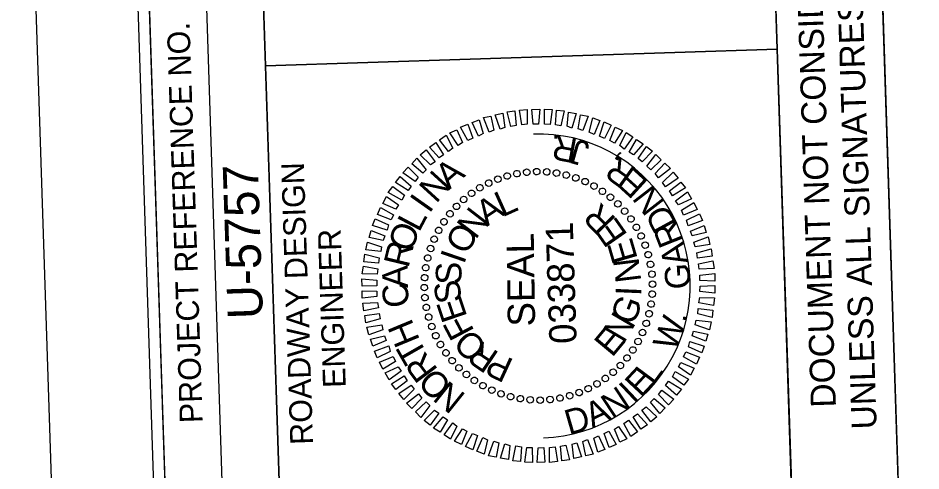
# Model space of a CAD drawing. Extents: x 1627314 to 1628469, y 762309 to 764245.
# Drawn here: x 1627314.2 to 1627512.6, y 763788.2 to 763887.6 of the extents above; entities that cross this region are included whole.
import ezdxf

# ---------------------------------------------------------------- set-up
doc = ezdxf.new("R2010")
doc.units = 0
for name, color, linetype in [('Old_Level_2', 7, 'Continuous'), ('Scratch_Level_0', 7, 'Continuous'), ('Sheet Data Field CELL', 7, 'Continuous'), ('Sheet Plot Border Inside CELL', 7, 'Continuous'), ('Sheet Plot Border Outside CELL', 7, 'Continuous'), ('Sheet Professional Seal CELL', 7, 'Continuous'), ('Sheet Profile CELL', 7, 'Continuous'), ('Sheet Profile Grid Major CELL', 7, 'Continuous'), ('Sheet Profile Grid Minor CELL', 7, 'Continuous'), ('Sheet Sticker Exception Certification CELL', 7, 'Continuous')]:
    doc.layers.add(name, color=color, linetype=linetype)

msp = doc.modelspace()

# ---------------------------------------------------------------- linework, layer by layer
at = {"layer": 'Old_Level_2'}
msp.add_lwpolyline([(1627507.79, 763781.61), (1627501.25, 763981.49), (1627565.16, 763983.58), (1627571.7, 763783.7)], close=True, dxfattribs=at)
at = {"layer": 'Scratch_Level_0'}
msp.add_arc((1627428.56, 763828.82), 33.36, 271.8735, 91.8735, dxfattribs=at)
at = {"layer": 'Sheet Plot Border Inside CELL'}
msp.add_lwpolyline([(1628446.34, 762357.53), (1628391.86, 764023.14), (1627337.33, 763988.65), (1627391.81, 762323.04)], close=True, dxfattribs=at)
at = {"layer": 'Sheet Plot Border Outside CELL'}
msp.add_lwpolyline([(1628469.21, 762345.27), (1628413.63, 764044.37), (1627314.22, 764008.4), (1627369.79, 762309.31)], close=True, dxfattribs=at)
at = {"layer": 'Sheet Professional Seal CELL'}
for p, q in [((1627419.59, 763852.29), (1627419.59, 763852.29)), ((1627421.67, 763852.96), (1627421.67, 763852.96)), ((1627423.86, 763853.43), (1627423.86, 763853.43)), ((1627426, 763853.8), (1627426, 763853.8)), ((1627428.19, 763853.92), (1627428.19, 763853.92)), ((1627430.4, 763853.84), (1627430.4, 763853.84)), ((1627432.56, 763853.57), (1627432.56, 763853.57)), ((1627434.67, 763853.18), (1627434.67, 763853.18)), ((1627436.79, 763852.55), (1627436.79, 763852.55)), ((1627415.7, 763850.36), (1627415.7, 763850.36)), ((1627417.62, 763851.43), (1627417.62, 763851.43)), ((1627438.82, 763851.72), (1627438.82, 763851.72)), ((1627440.8, 763850.78), (1627440.8, 763850.78)), ((1627413.84, 763849.15), (1627413.84, 763849.15)), ((1627442.64, 763849.59), (1627442.64, 763849.59)), ((1627444.44, 763848.3), (1627444.44, 763848.3)), ((1627410.53, 763846.29), (1627410.53, 763846.29)), ((1627412.13, 763847.84), (1627412.13, 763847.84)), ((1627446.03, 763846.85), (1627446.03, 763846.85)), ((1627409.08, 763844.69), (1627409.08, 763844.69)), ((1627447.59, 763845.25), (1627447.59, 763845.25)), ((1627407.79, 763842.9), (1627407.79, 763842.9)), ((1627448.89, 763843.54), (1627448.89, 763843.54)), ((1627406.6, 763841.06), (1627406.6, 763841.06)), ((1627450.1, 763841.68), (1627450.1, 763841.68)), ((1627405.67, 763839.08), (1627405.67, 763839.08)), ((1627451.17, 763839.77), (1627451.17, 763839.77)), ((1627404.83, 763837.05), (1627404.83, 763837.05)), ((1627452.03, 763837.79), (1627452.03, 763837.79)), ((1627404.2, 763834.93), (1627404.2, 763834.93)), ((1627452.7, 763835.71), (1627452.7, 763835.71)), ((1627403.82, 763832.81), (1627403.82, 763832.81)), ((1627453.17, 763833.53), (1627453.17, 763833.53)), ((1627403.54, 763830.65), (1627403.54, 763830.65)), ((1627453.54, 763831.39), (1627453.54, 763831.39)), ((1627403.46, 763828.45), (1627403.46, 763828.45)), ((1627428.56, 763828.82), (1627428.56, 763828.82)), ((1627453.66, 763829.19), (1627453.66, 763829.19)), ((1627453.59, 763826.99), (1627453.59, 763826.99)), ((1627403.58, 763826.25), (1627403.58, 763826.25)), ((1627453.31, 763824.83), (1627453.31, 763824.83)), ((1627403.95, 763824.11), (1627403.95, 763824.11)), ((1627452.93, 763822.71), (1627452.93, 763822.71)), ((1627404.43, 763821.93), (1627404.43, 763821.93)), ((1627452.3, 763820.59), (1627452.3, 763820.59)), ((1627405.09, 763819.85), (1627405.09, 763819.85)), ((1627451.46, 763818.56), (1627451.46, 763818.56)), ((1627405.96, 763817.88), (1627405.96, 763817.88)), ((1627450.53, 763816.58), (1627450.53, 763816.58)), ((1627407.02, 763815.96), (1627407.02, 763815.96)), ((1627449.33, 763814.74), (1627449.33, 763814.74)), ((1627408.23, 763814.1), (1627408.23, 763814.1)), ((1627448.04, 763812.95), (1627448.04, 763812.95)), ((1627409.54, 763812.39), (1627409.54, 763812.39)), ((1627411.09, 763810.79), (1627411.09, 763810.79)), ((1627446.59, 763811.35), (1627446.59, 763811.35)), ((1627412.69, 763809.34), (1627412.69, 763809.34)), ((1627444.99, 763809.8), (1627444.99, 763809.8)), ((1627414.49, 763808.05), (1627414.49, 763808.05)), ((1627416.33, 763806.86), (1627416.33, 763806.86)), ((1627441.42, 763807.28), (1627441.42, 763807.28)), ((1627443.29, 763808.49), (1627443.29, 763808.49)), ((1627418.31, 763805.92), (1627418.31, 763805.92)), ((1627420.34, 763805.09), (1627420.34, 763805.09)), ((1627435.46, 763804.68), (1627435.46, 763804.68)), ((1627437.54, 763805.35), (1627437.54, 763805.35)), ((1627439.51, 763806.22), (1627439.51, 763806.22)), ((1627422.46, 763804.46), (1627422.46, 763804.46)), ((1627424.57, 763804.08), (1627424.57, 763804.08)), ((1627426.73, 763803.8), (1627426.73, 763803.8)), ((1627428.93, 763803.72), (1627428.93, 763803.72)), ((1627431.13, 763803.84), (1627431.13, 763803.84)), ((1627433.27, 763804.21), (1627433.27, 763804.21))]:
    msp.add_line(p, q, dxfattribs=at)
for points in [[(1627417.75, 763862.59), (1627416.5, 763865.75), (1627418.14, 763866.1), (1627418.79, 763862.97)], [(1627420.13, 763863.26), (1627419.08, 763866.38), (1627420.77, 763866.74), (1627421.17, 763863.6)], [(1627422.52, 763863.79), (1627421.71, 763867.02), (1627423.41, 763867.22), (1627423.71, 763864.03)], [(1627424.91, 763864.17), (1627424.4, 763867.41), (1627426.1, 763867.56), (1627426.1, 763864.31)], [(1627427.4, 763864.3), (1627427.15, 763867.55), (1627428.85, 763867.6), (1627428.6, 763864.34)], [(1627429.9, 763864.33), (1627429.9, 763867.59), (1627431.55, 763867.54), (1627431.11, 763864.27)], [(1627432.31, 763864.16), (1627432.51, 763867.37), (1627434.21, 763867.23), (1627433.52, 763863.95)], [(1627434.87, 763863.85), (1627435.17, 763866.96), (1627436.88, 763866.66), (1627435.93, 763863.48)], [(1627437.29, 763863.28), (1627437.84, 763866.39), (1627439.5, 763866.1), (1627438.35, 763862.91)], [(1627413.06, 763860.73), (1627411.47, 763863.63), (1627413.04, 763864.33), (1627414.15, 763861.27)], [(1627415.38, 763861.71), (1627413.98, 763864.71), (1627415.51, 763865.31), (1627416.41, 763862.24)], [(1627439.72, 763862.6), (1627440.51, 763865.73), (1627442.08, 763865.13), (1627440.78, 763862.09)], [(1627441.95, 763861.68), (1627442.99, 763864.81), (1627444.57, 763864.11), (1627443.06, 763861.21)], [(1627410.95, 763859.66), (1627409.11, 763862.4), (1627410.63, 763863.1), (1627411.88, 763860.29)], [(1627444.28, 763860.75), (1627445.43, 763863.64), (1627447.01, 763862.94), (1627445.25, 763860.18)], [(1627446.47, 763859.62), (1627447.87, 763862.47), (1627449.31, 763861.52), (1627447.39, 763858.85)], [(1627406.78, 763856.92), (1627404.6, 763859.3), (1627406.02, 763860.3), (1627407.71, 763857.56)], [(1627408.79, 763858.29), (1627406.8, 763860.88), (1627408.27, 763861.88), (1627409.77, 763859.02)], [(1627448.51, 763858.19), (1627450.12, 763860.94), (1627451.61, 763860.04), (1627449.48, 763857.57)], [(1627404.88, 763855.36), (1627402.56, 763857.59), (1627403.87, 763858.68), (1627405.86, 763856.09)], [(1627450.46, 763856.75), (1627452.33, 763859.41), (1627453.66, 763858.36), (1627451.38, 763856.08)], [(1627403.14, 763853.55), (1627400.72, 763855.63), (1627401.88, 763856.86), (1627403.92, 763854.33)], [(1627452.42, 763855.07), (1627454.38, 763857.68), (1627455.57, 763856.47), (1627453.24, 763854.29)], [(1627401.45, 763851.7), (1627398.79, 763853.66), (1627399.95, 763854.9), (1627402.17, 763852.67)], [(1627454.22, 763853.47), (1627456.35, 763855.74), (1627457.59, 763854.58), (1627454.95, 763852.55)], [(1627399.96, 763849.75), (1627397.16, 763851.51), (1627398.21, 763852.84), (1627400.63, 763850.72)], [(1627455.84, 763851.53), (1627458.16, 763853.75), (1627459.26, 763852.44), (1627456.52, 763850.6)], [(1627398.53, 763847.65), (1627395.58, 763849.3), (1627396.58, 763850.64), (1627399.1, 763848.77)], [(1627457.4, 763849.68), (1627459.89, 763851.61), (1627460.88, 763850.34), (1627458.03, 763848.6)], [(1627397.25, 763845.66), (1627394.35, 763846.91), (1627395.15, 763848.44), (1627397.82, 763846.63)], [(1627458.72, 763847.52), (1627461.36, 763849.45), (1627462.21, 763847.93), (1627459.35, 763846.59)], [(1627459.99, 763845.41), (1627462.73, 763847.1), (1627463.48, 763845.57), (1627460.47, 763844.32)], [(1627396.17, 763843.32), (1627393.18, 763844.47), (1627393.83, 763846.05), (1627396.69, 763844.44)], [(1627461.11, 763843.24), (1627463.97, 763844.64), (1627464.61, 763843.16), (1627461.45, 763842)], [(1627395.3, 763841.04), (1627392.11, 763842.09), (1627392.66, 763843.51), (1627395.61, 763842.2)], [(1627394.47, 763838.76), (1627391.35, 763839.41), (1627391.8, 763840.98), (1627394.79, 763839.82)], [(1627461.99, 763840.82), (1627464.95, 763842.07), (1627465.45, 763840.53), (1627462.37, 763839.78)], [(1627393.9, 763836.34), (1627390.63, 763836.74), (1627390.98, 763838.45), (1627394.11, 763837.4)], [(1627462.72, 763838.44), (1627465.83, 763839.6), (1627466.24, 763837.91), (1627463, 763837.4)], [(1627463.35, 763836.06), (1627466.52, 763836.97), (1627466.72, 763835.32), (1627463.53, 763834.87)], [(1627393.43, 763833.78), (1627390.22, 763834.12), (1627390.42, 763835.78), (1627393.54, 763834.98)], [(1627393.11, 763831.36), (1627389.86, 763831.46), (1627390.1, 763833.12), (1627393.27, 763832.57)], [(1627463.72, 763833.67), (1627466.9, 763834.33), (1627467.16, 763832.64), (1627463.91, 763832.48)], [(1627393.04, 763828.86), (1627389.8, 763828.75), (1627389.79, 763830.4), (1627393.05, 763830.06)], [(1627464.06, 763831.18), (1627467.3, 763831.54), (1627467.3, 763829.89), (1627464.04, 763829.98)], [(1627464.08, 763828.78), (1627467.33, 763828.89), (1627467.34, 763827.24), (1627464.07, 763827.58)], [(1627393.07, 763826.46), (1627389.83, 763826.1), (1627389.83, 763827.75), (1627393.08, 763827.66)], [(1627393.4, 763823.97), (1627390.22, 763823.32), (1627389.97, 763825.01), (1627393.21, 763825.16)], [(1627464.02, 763826.28), (1627467.27, 763826.19), (1627467.02, 763824.53), (1627463.85, 763825.07)], [(1627393.78, 763821.58), (1627390.61, 763820.68), (1627390.41, 763822.32), (1627393.59, 763822.78)], [(1627463.69, 763823.87), (1627466.91, 763823.52), (1627466.71, 763821.87), (1627463.58, 763822.66)], [(1627463.23, 763821.3), (1627466.49, 763820.91), (1627466.15, 763819.2), (1627463.01, 763820.24)], [(1627394.41, 763819.2), (1627391.3, 763818.05), (1627390.89, 763819.74), (1627394.13, 763820.24)], [(1627462.66, 763818.88), (1627465.78, 763818.23), (1627465.33, 763816.67), (1627462.34, 763817.82)], [(1627395.14, 763816.82), (1627392.18, 763815.57), (1627391.68, 763817.11), (1627394.75, 763817.86)], [(1627461.83, 763816.6), (1627465.02, 763815.56), (1627464.46, 763814.14), (1627461.52, 763815.44)], [(1627396.02, 763814.4), (1627393.16, 763813.01), (1627392.51, 763814.49), (1627395.68, 763815.64)], [(1627397.14, 763812.24), (1627394.39, 763810.54), (1627393.64, 763812.07), (1627396.65, 763813.32)], [(1627460.95, 763814.32), (1627463.94, 763813.17), (1627463.3, 763811.6), (1627460.44, 763813.21)], [(1627398.41, 763810.13), (1627395.77, 763808.19), (1627394.92, 763809.71), (1627397.78, 763811.06)], [(1627459.88, 763811.99), (1627462.77, 763810.73), (1627461.97, 763809.2), (1627459.31, 763811.02)], [(1627399.73, 763807.97), (1627397.24, 763806.04), (1627396.25, 763807.3), (1627399.09, 763809.05)], [(1627458.6, 763809.99), (1627461.55, 763808.34), (1627460.54, 763807.01), (1627458.03, 763808.87)], [(1627401.29, 763806.12), (1627398.96, 763803.89), (1627397.87, 763805.21), (1627400.61, 763807.05)], [(1627457.16, 763807.9), (1627459.97, 763806.14), (1627458.92, 763804.8), (1627456.49, 763806.92)], [(1627402.91, 763804.17), (1627400.78, 763801.9), (1627399.54, 763803.06), (1627402.18, 763805.1)], [(1627455.68, 763805.95), (1627458.34, 763803.98), (1627457.18, 763802.74), (1627454.96, 763804.97)], [(1627404.71, 763802.58), (1627402.74, 763799.96), (1627401.55, 763801.17), (1627403.88, 763803.35)], [(1627453.99, 763804.09), (1627456.4, 763802.02), (1627455.24, 763800.78), (1627453.21, 763803.31)], [(1627406.67, 763800.89), (1627404.8, 763798.23), (1627403.47, 763799.29), (1627405.74, 763801.56)], [(1627450.34, 763800.72), (1627452.52, 763798.34), (1627451.1, 763797.34), (1627449.41, 763800.09)], [(1627452.24, 763802.28), (1627454.57, 763800.06), (1627453.25, 763798.96), (1627451.27, 763801.55)], [(1627408.61, 763799.45), (1627407, 763796.7), (1627405.52, 763797.6), (1627407.64, 763800.07)], [(1627410.66, 763798.02), (1627409.25, 763795.17), (1627407.82, 763796.13), (1627409.74, 763798.79)], [(1627448.34, 763799.35), (1627450.32, 763796.77), (1627448.86, 763795.77), (1627447.36, 763798.62)], [(1627412.85, 763796.89), (1627411.69, 763794), (1627410.12, 763794.7), (1627411.88, 763797.46)], [(1627444.07, 763796.91), (1627445.66, 763794.01), (1627444.08, 763793.31), (1627442.98, 763796.38)], [(1627446.18, 763797.98), (1627448.02, 763795.24), (1627446.49, 763794.54), (1627445.25, 763797.35)], [(1627415.18, 763795.97), (1627414.13, 763792.83), (1627412.56, 763793.53), (1627414.06, 763796.43)], [(1627417.41, 763795.04), (1627416.61, 763791.91), (1627415.04, 763792.51), (1627416.34, 763795.55)], [(1627419.84, 763794.37), (1627419.29, 763791.25), (1627417.63, 763791.54), (1627418.77, 763794.73)], [(1627439.37, 763795.06), (1627440.63, 763791.9), (1627438.99, 763791.54), (1627438.34, 763794.67)], [(1627441.75, 763795.93), (1627443.14, 763792.93), (1627441.61, 763792.33), (1627440.71, 763795.4)], [(1627422.26, 763793.8), (1627421.96, 763790.69), (1627420.25, 763790.98), (1627421.19, 763794.16)], [(1627424.82, 763793.48), (1627424.62, 763790.27), (1627422.92, 763790.42), (1627423.61, 763793.69)], [(1627427.22, 763793.31), (1627427.23, 763790.06), (1627425.58, 763790.1), (1627426.02, 763793.37)], [(1627429.72, 763793.34), (1627429.98, 763790.1), (1627428.28, 763790.04), (1627428.52, 763793.3)], [(1627432.22, 763793.47), (1627432.73, 763790.24), (1627431.03, 763790.08), (1627431.03, 763793.33)], [(1627434.61, 763793.85), (1627435.42, 763790.63), (1627433.72, 763790.42), (1627433.42, 763793.61)], [(1627436.99, 763794.38), (1627438.05, 763791.26), (1627436.36, 763790.91), (1627435.95, 763794.04)]]:
    msp.add_lwpolyline(points, close=True, dxfattribs=at)
for centre, major_axis in [((1627423.83, 763853.45), (-0.136, 0.707)), ((1627426, 763853.77), (-0.074, 0.716)), ((1627428.18, 763853.9), (-0.011, 0.72)), ((1627430.37, 763853.84), (0.052, 0.718)), ((1627432.54, 763853.58), (0.114, 0.711)), ((1627419.63, 763852.26), (-0.257, 0.673)), ((1627421.7, 763852.95), (-0.197, 0.693)), ((1627434.68, 763853.14), (0.176, 0.698)), ((1627436.78, 763852.52), (0.236, 0.68)), ((1627438.82, 763851.71), (0.294, 0.657)), ((1627415.69, 763850.35), (-0.369, 0.618)), ((1627417.62, 763851.39), (-0.314, 0.648)), ((1627440.77, 763850.73), (0.35, 0.629)), ((1627442.63, 763849.58), (0.404, 0.596)), ((1627412.15, 763847.79), (-0.471, 0.544)), ((1627413.87, 763849.14), (-0.422, 0.583)), ((1627444.39, 763848.28), (0.454, 0.559)), ((1627410.56, 763846.28), (-0.517, 0.501)), ((1627446.03, 763846.82), (0.501, 0.517)), ((1627409.11, 763844.65), (-0.559, 0.454)), ((1627447.53, 763845.23), (0.544, 0.471)), ((1627448.89, 763843.52), (0.583, 0.422)), ((1627407.8, 763842.89), (-0.596, 0.404)), ((1627450.09, 763841.69), (0.618, 0.369)), ((1627406.66, 763841.03), (-0.629, 0.35)), ((1627451.13, 763839.77), (0.648, 0.314)), ((1627405.67, 763839.07), (-0.657, 0.294)), ((1627452, 763837.76), (0.673, 0.257)), ((1627404.87, 763837.04), (-0.68, 0.236)), ((1627452.69, 763835.68), (0.693, 0.197)), ((1627404.24, 763834.94), (-0.698, 0.176)), ((1627403.8, 763832.8), (-0.711, 0.114)), ((1627453.19, 763833.55), (0.707, 0.136)), ((1627403.55, 763830.63), (-0.718, 0.052)), ((1627453.51, 763831.39), (0.716, 0.074)), ((1627403.49, 763828.44), (-0.72, -0.011)), ((1627453.64, 763829.2), (0.72, 0.011)), ((1627403.62, 763826.26), (-0.716, -0.074)), ((1627453.58, 763827.02), (0.718, -0.052)), ((1627403.93, 763824.09), (-0.707, -0.136)), ((1627453.33, 763824.84), (0.711, -0.114)), ((1627404.44, 763821.96), (-0.693, -0.197)), ((1627452.89, 763822.7), (0.698, -0.176)), ((1627405.13, 763819.89), (-0.673, -0.257)), ((1627452.26, 763820.6), (0.68, -0.236)), ((1627406, 763817.88), (-0.648, -0.314)), ((1627451.45, 763818.57), (0.657, -0.294)), ((1627407.04, 763815.95), (-0.618, -0.369)), ((1627450.47, 763816.61), (0.629, -0.35)), ((1627408.24, 763814.12), (-0.583, -0.422)), ((1627449.32, 763814.75), (0.596, -0.404)), ((1627409.6, 763812.41), (-0.544, -0.471)), ((1627448.02, 763813), (0.559, -0.454)), ((1627411.1, 763810.82), (-0.501, -0.517)), ((1627444.98, 763809.86), (0.471, -0.544)), ((1627446.57, 763811.36), (0.517, -0.501)), ((1627412.74, 763809.37), (-0.454, -0.559)), ((1627414.49, 763808.06), (-0.404, -0.596)), ((1627443.26, 763808.5), (0.422, -0.583)), ((1627416.36, 763806.91), (-0.35, -0.629)), ((1627418.31, 763805.93), (-0.294, -0.657)), ((1627439.51, 763806.26), (0.314, -0.648)), ((1627441.43, 763807.3), (0.369, -0.618)), ((1627420.35, 763805.13), (-0.236, -0.68)), ((1627422.44, 763804.5), (-0.176, -0.698)), ((1627424.59, 763804.06), (-0.114, -0.711)), ((1627431.13, 763803.87), (0.074, -0.716)), ((1627433.29, 763804.19), (0.136, -0.707)), ((1627435.42, 763804.7), (0.197, -0.693)), ((1627437.5, 763805.39), (0.257, -0.673)), ((1627426.76, 763803.81), (-0.052, -0.718)), ((1627428.95, 763803.74), (0.011, -0.72))]:
    msp.add_ellipse(centre, major_axis=major_axis, ratio=0.999708, dxfattribs=at)
at = {"layer": 'Sheet Profile CELL'}
for p, q in [((1627359.37, 763776.71), (1627352.83, 763976.65)), ((1627368.59, 763877.11), (1627480.98, 763880.79))]:
    msp.add_line(p, q, dxfattribs=at)
for points in [[(1627340.28, 763976.24), (1627389.32, 762477.04), (1628438.76, 762511.37), (1628389.72, 764010.57)], [(1627368.59, 763877.11), (1627365.32, 763977.06), (1627477.76, 763980.74), (1627481.03, 763880.79)], [(1627346.82, 763776.3), (1627340.28, 763976.24), (1627365.32, 763977.06), (1627371.86, 763777.12)], [(1627371.86, 763777.12), (1627368.59, 763877.11), (1627481.03, 763880.79), (1627484.3, 763780.79)]]:
    msp.add_lwpolyline(points, close=True, dxfattribs=at)
at = {"layer": 'Sheet Profile Grid Major CELL'}
msp.add_lwpolyline([(1627864.53, 763242.99), (1627862.9, 763292.96), (1627363.17, 763276.61), (1627361.53, 763326.59), (1627861.27, 763342.93), (1627859.63, 763392.91), (1627359.9, 763376.56), (1627358.26, 763426.53), (1627858, 763442.88), (1627856.36, 763492.85), (1627356.63, 763476.51), (1627354.99, 763526.48), (1627854.73, 763542.83), (1627853.09, 763592.8), (1627353.36, 763576.45), (1627351.73, 763626.43), (1627851.46, 763642.77), (1627849.82, 763692.75), (1627350.09, 763676.4), (1627348.46, 763726.37), (1627848.19, 763742.72), (1627846.55, 763792.69), (1627346.82, 763776.35), (1627345.96, 763802.63)], dxfattribs=at)
at = {"layer": 'Sheet Sticker Exception Certification CELL'}
for p, q in [((1627501.25, 763981.49), (1627507.79, 763781.56)), ((1627501.25, 763981.49), (1627507.79, 763781.56)), ((1627484.3, 763780.79), (1627477.76, 763980.72)), ((1627484.3, 763780.79), (1627477.76, 763980.72))]:
    msp.add_line(p, q, dxfattribs=at)

# ---------------------------------------------------------------- texts
at = {"layer": 'Sheet Data Field CELL'}
msp.add_text('U-5757', height=7.75, rotation=91.8735, dxfattribs=at).set_placement((1627368.04, 763821.64))
at = {"layer": 'Sheet Professional Seal CELL'}
for s, height, rotation, p in [('A', 5.64, 40.4906, (1627408.92, 763849.79)), ('N', 5.64, 47.6924, (1627406.07, 763846.75)), ('I', 5.64, 54.8936, (1627404.59, 763844.55)), ('L', 5.64, 24.2743, (1627420.62, 763843.82)), ('A', 5.64, 33.6337, (1627417.23, 763841.76)), ('R', 5.64, 134.3549, (1627445.84, 763843.49)), ('N', 5.64, 52.3501, (1627414.73, 763838.82)), ('O', 5.64, 69.2946, (1627400.62, 763835.96)), ('L', 5.64, 62.0943, (1627402.32, 763840.42)), ('E', 5.64, 124.9976, (1627448.31, 763840.02)), ('O', 5.64, 61.707, (1627412.84, 763835.41)), ('R', 5.64, 76.4946, (1627399.98, 763832.59)), ('SEAL', 5.998, 90.8735, (1627427.85, 763819.94)), ('E', 5.64, 106.2852, (1627450.43, 763834.79)), ('I', 5.64, 71.0631, (1627412.21, 763833.39)), ('N', 5.64, 96.9299, (1627451.19, 763829.86)), ('A', 5.64, 90.8938, (1627399.91, 763828.38)), ('S', 5.64, 89.7739, (1627411.65, 763829.07)), ('C', 5.64, 98.0933, (1627400.34, 763824.45)), ('S', 5.64, 99.1291, (1627411.81, 763825.47)), ('E', 5.64, 108.4845, (1627412.98, 763822.06)), ('I', 5.64, 87.5747, (1627451.15, 763826.51)), ('G', 5.64, 68.8637, (1627449.47, 763819.9)), ('N', 5.64, 59.5074, (1627447.34, 763816.03)), ('H', 5.64, 112.4929, (1627402.59, 763816.92)), ('F', 5.64, 117.8405, (1627414.58, 763818.91)), ('O', 5.64, 136.5547, (1627417.64, 763815.71)), ('E', 5.64, 50.1504, (1627444.74, 763812.94)), ('R', 5.64, 145.9131, (1627420.14, 763814.04)), ('T', 5.64, 119.6932, (1627404.34, 763813.72)), ('R', 5.64, 126.894, (1627406.65, 763810.4)), ('P', 5.64, 155.2724, (1627423.39, 763812.54)), ('O', 5.64, 134.0952, (1627409.87, 763807.05)), ('N', 5.64, 141.297, (1627412.84, 763804.84))]:
    msp.add_text(s, height=height, rotation=rotation, dxfattribs=at).set_placement(p)
at = {"layer": 'Sheet Profile CELL'}
for s, height, p in [('PROJECT REFERENCE NO.', 5.0001, (1627354.78, 763798.78)), ('ROADWAY DESIGN', 5.0001, (1627379.05, 763794.02)), ('ENGINEER', 5, (1627386.24, 763806.51))]:
    msp.add_text(s, height=height, rotation=91.8735, dxfattribs=at).set_placement(p)
at = {"layer": 'Sheet Profile Grid Minor CELL'}
for s, height, rotation, p in [('R', 5.5, 169.2275, (1627437.42, 763861.1)), ('.', 5.5, 176.154, (1627433.46, 763861.93)), ('J', 5.5, 164.359, (1627440.12, 763860.23)), (',', 5.5, 151.1787, (1627446.98, 763856.77)), ('R', 5.5, 144.2523, (1627450.22, 763854.34)), ('E', 5.5, 137.6693, (1627453, 763851.69)), ('N', 5.5, 127.7376, (1627456.58, 763847.14)), ('D', 5.5, 118.5929, (1627459.13, 763842.45)), ('033871', 5.998, 91.8735, (1627436.99, 763816.19)), ('R', 5.5, 111.6665, (1627460.55, 763838.67)), ('A', 5.5, 103.4807, (1627461.63, 763834.01)), ('G', 5.5, 93.549, (1627462.03, 763828.23)), ('W', 5.5, 68.7626, (1627458.7, 763814.25)), ('.', 5.5, 80.3687, (1627461.01, 763820.61)), ('E', 5.5, 46.9243, (1627451.12, 763804.09)), ('L', 5.5, 53.5073, (1627453.8, 763806.84)), ('N', 5.5, 33.4721, (1627444.74, 763799.52)), ('I', 5.5, 43.4038, (1627449.55, 763802.75)), ('A', 5.5, 25.2863, (1627440.41, 763797.52)), ('D', 5.5, 16.1417, (1627435.28, 763796.03))]:
    msp.add_text(s, height=height, rotation=rotation, dxfattribs=at).set_placement(p)
at = {"layer": 'Sheet Sticker Exception Certification CELL'}
for s, p in [('UNLESS ALL SIGNATURES COMPLETED', (1627502.91, 763797.41)), ('UNLESS ALL SIGNATURES COMPLETED', (1627502.91, 763797.41)), ('DOCUMENT NOT CONSIDERED FINAL', (1627493.95, 763802.19)), ('DOCUMENT NOT CONSIDERED FINAL', (1627493.95, 763802.19))]:
    msp.add_text(s, height=5.5, rotation=91.8735, dxfattribs=at).set_placement(p)

doc.saveas('drawing.dxf')
